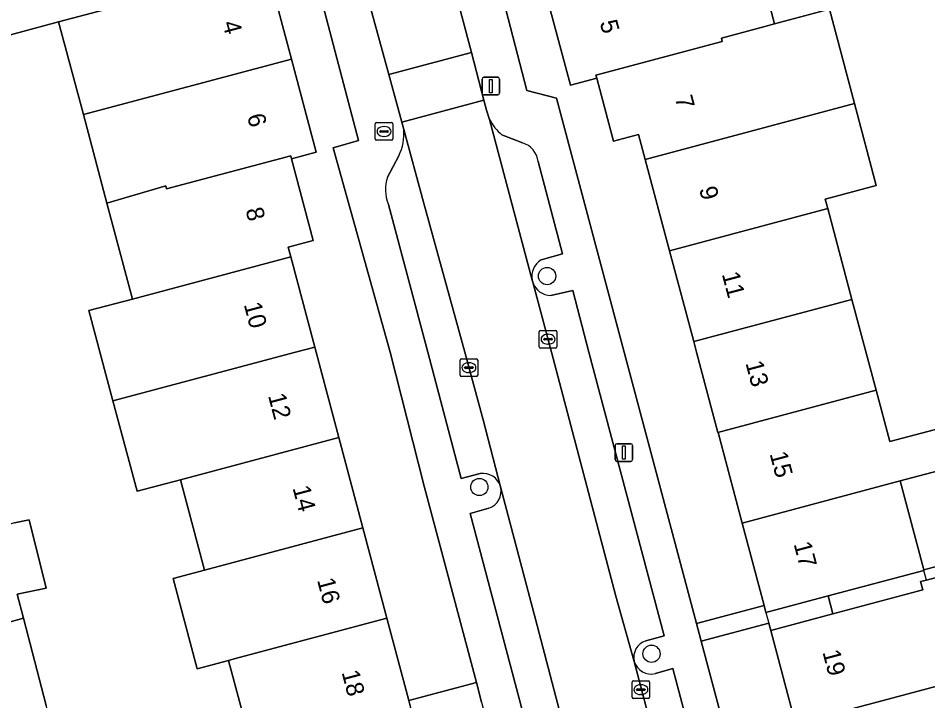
# Model space of a CAD drawing. Extents: x 162542 to 163147, y 380779 to 381521.
# Drawn here: x 162725.1 to 162776.8, y 380980.2 to 381019 of the extents above; entities that cross this region are included whole.
import ezdxf

# ---------------------------------------------------------------- set-up
doc = ezdxf.new("R2010")
doc.units = 0
for name, color, linetype in [('IMGEO_Boom', 7, 'Continuous'), ('IMGEO_Brandkraan', 7, 'Continuous'), ('IMGEO_Erf', 7, 'Continuous'), ('IMGEO_Kolk', 7, 'Continuous'), ('IMGEO_Lichtmast', 7, 'Continuous'), ('IMGEO_Pand', 7, 'Continuous'), ('IMGEO_Pand_nummerreeks', 7, 'Continuous'), ('IMGEO_Pand_overbouw', 7, 'Continuous'), ('IMGEO_Parkeervlak_open', 7, 'Continuous'), ('IMGEO_Rijbaan_lokaal_open', 7, 'Continuous'), ('IMGEO_Voetpad_open', 7, 'Continuous')]:
    doc.layers.add(name, color=color, linetype=linetype)

msp = doc.modelspace()

# ---------------------------------------------------------------- linework, layer by layer
at = {"layer": 'IMGEO_Boom'}
for centre in [(162755.19, 381004.332), (162751.341, 380992.348), (162761.127, 380982.876)]:
    msp.add_circle(centre, 0.489, dxfattribs=at)
at = {"layer": 'IMGEO_Brandkraan'}
for p, q in [((162745.423, 381012.122), (162745.423, 381012.974)), ((162745.498, 381013.048), (162746.35, 381013.048)), ((162745.911, 381012.828), (162745.936, 381012.828)), ((162746.424, 381012.974), (162746.424, 381012.122)), ((162745.682, 381012.542), (162745.682, 381012.554)), ((162746.12, 381012.505), (162745.722, 381012.505)), ((162745.725, 381012.591), (162746.123, 381012.591)), ((162745.934, 381012.268), (162745.909, 381012.268)), ((162746.166, 381012.554), (162746.166, 381012.542)), ((162746.35, 381012.048), (162745.498, 381012.048))]:
    msp.add_line(p, q, dxfattribs=at)
for points in [[(162745.423, 381012.122), (162745.423, 381012.974)], [(162745.498, 381013.048), (162746.35, 381013.048)], [(162746.424, 381012.974), (162746.424, 381012.122)], [(162746.35, 381012.048), (162745.498, 381012.048)]]:
    msp.add_lwpolyline(points, dxfattribs=at)
for centre, radius, start, end in [((162745.5, 381012.972), 0.0765, 91.552, 178.448), ((162745.5, 381012.972), 0.0765, 91.552, 178.448), ((162746.348, 381012.972), 0.0765, 1.552, 88.448), ((162746.348, 381012.972), 0.0765, 1.552, 88.448), ((162745.722, 381012.551), 0.0403, 85.8775, 175.7526), ((162745.719, 381012.541), 0.0366, 178.938, 274.7102), ((162746.123, 381012.548), 0.043, 264.8664, 352.4533), ((162746.127, 381012.553), 0.0386, 1.7309, 96.639), ((162745.5, 381012.124), 0.0765, 181.552, 268.448), ((162745.5, 381012.124), 0.0765, 181.552, 268.448), ((162746.348, 381012.124), 0.0765, 271.552, 358.448), ((162746.348, 381012.124), 0.0765, 271.552, 358.448)]:
    msp.add_arc(centre, radius, start, end, dxfattribs=at)
for centre, major_axis, ratio, start_param, end_param in [((162745.91, 381012.548), (-0.387, 0.002), 0.722429, 4.712389, 7.853982), ((162745.935, 381012.548), (-0.39, 0.002), 0.717154, 1.570796, 4.712389)]:
    msp.add_ellipse(centre, major_axis=major_axis, ratio=ratio, start_param=start_param, end_param=end_param, dxfattribs=at)
at = {"layer": 'IMGEO_Erf'}
for points in [[(162762.153, 381005.771), (162760.77, 381010.962), (162760.394, 381012.373), (162758.966, 381011.993), (162758.011, 381015.58), (162756.517, 381015.182), (162755.104, 381020.488), (162753.691, 381025.795), (162751.366, 381025.19), (162754.046, 381014.881), (162755.726, 381014.447), (162759.578, 381000), (162763.686, 380984.593), (162767.521, 380985.616), (162766.274, 380990.297), (162764.904, 380995.443), (162764.901, 380995.452), (162764.901, 380995.454), (162763.69, 381000), (162763.527, 381000.613)], [(162746.28, 381000), (162743.026, 381011.614), (162744.463, 381012.029), (162741.713, 381022.565), (162739.263, 381021.926), (162740.667, 381016.648), (162742.071, 381011.368), (162740.662, 381010.993), (162741.895, 381006.359), (162740.471, 381005.98), (162740.62, 381005.421), (162741.985, 381000.29), (162742.062, 381000), (162743.35, 380995.158), (162744.715, 380990.028), (162746.08, 380984.896), (162747.326, 380980.213), (162751.174, 380981.237), (162748.205, 380992.388)], [(162776.104, 380953.39), (162774.717, 380958.599), (162773.391, 380963.577), (162772.064, 380968.558), (162770.678, 380973.763), (162769.31, 380978.899), (162767.898, 380984.203), (162767.79, 380984.608), (162763.955, 380983.585), (162780.617, 380921.086), (162784.437, 380922.105), (162783.04, 380927.349), (162781.653, 380932.556), (162780.266, 380937.765), (162778.879, 380942.973), (162777.492, 380948.181)]]:
    msp.add_lwpolyline(points, close=True, dxfattribs=at)
for points in [[(162766.804, 381023.607), (162768.122, 381018.658), (162771.235, 381019.487), (162772.661, 381014.131), (162773.9, 381009.48), (162770.994, 381008.706), (162771.138, 381008.166), (162772.512, 381003.008), (162773.886, 380997.849), (162774.665, 380994.928), (162777.543, 380995.694)], [(162738.516, 380977.142), (162737.088, 380982.502), (162735.304, 380982.026), (162733.937, 380987.156), (162735.722, 380987.632), (162734.356, 380992.762), (162731.885, 380992.104), (162730.518, 380997.236), (162729.151, 381002.367), (162731.622, 381003.025), (162730.172, 381008.47), (162728.832, 381013.503), (162727.427, 381018.777), (162715.091, 381015.44)], [(162778.139, 380993.459), (162775.259, 380992.692), (162776.605, 380987.639), (162788.533, 380990.817)], [(162724.914, 380990.308), (162725.758, 380990.483), (162726.716, 380986.611), (162725.08, 380986.261), (162725.435, 380984.891), (162726.721, 380979.933)]]:
    msp.add_lwpolyline(points, dxfattribs=at)
at = {"layer": 'IMGEO_Kolk'}
for p, q in [((162754.744, 381000.318), (162754.744, 381001.17)), ((162754.819, 381001.244), (162755.671, 381001.244)), ((162755.232, 381001.024), (162755.257, 381001.024)), ((162755.745, 381001.17), (162755.745, 381000.318)), ((162755.003, 381000.738), (162755.003, 381000.75)), ((162755.441, 381000.701), (162755.043, 381000.701)), ((162755.046, 381000.787), (162755.444, 381000.787)), ((162755.255, 381000.464), (162755.23, 381000.464)), ((162755.487, 381000.75), (162755.487, 381000.738)), ((162755.671, 381000.244), (162754.819, 381000.244)), ((162750.245, 380998.705), (162750.245, 380999.557)), ((162750.32, 380999.631), (162751.172, 380999.631)), ((162750.733, 380999.411), (162750.758, 380999.411)), ((162751.246, 380999.557), (162751.246, 380998.705)), ((162750.504, 380999.125), (162750.504, 380999.137)), ((162750.942, 380999.088), (162750.544, 380999.088)), ((162750.547, 380999.174), (162750.945, 380999.174)), ((162750.756, 380998.851), (162750.731, 380998.851)), ((162750.988, 380999.137), (162750.988, 380999.125)), ((162751.172, 380998.631), (162750.32, 380998.631)), ((162760.018, 380980.407), (162760.018, 380981.259)), ((162760.093, 380981.333), (162760.945, 380981.333)), ((162761.019, 380981.259), (162761.019, 380980.407)), ((162760.277, 380980.827), (162760.277, 380980.839)), ((162760.715, 380980.79), (162760.317, 380980.79)), ((162760.32, 380980.876), (162760.718, 380980.876)), ((162760.506, 380981.113), (162760.531, 380981.113)), ((162760.761, 380980.839), (162760.761, 380980.827)), ((162760.945, 380980.333), (162760.093, 380980.333)), ((162760.529, 380980.553), (162760.504, 380980.553))]:
    msp.add_line(p, q, dxfattribs=at)
for points in [[(162754.744, 381000.318), (162754.744, 381001.17)], [(162754.819, 381001.244), (162755.671, 381001.244)], [(162755.745, 381001.17), (162755.745, 381000.318)], [(162755.671, 381000.244), (162754.819, 381000.244)], [(162750.245, 380998.705), (162750.245, 380999.557)], [(162750.32, 380999.631), (162751.172, 380999.631)], [(162751.246, 380999.557), (162751.246, 380998.705)], [(162751.172, 380998.631), (162750.32, 380998.631)], [(162760.018, 380980.407), (162760.018, 380981.259)], [(162760.093, 380981.333), (162760.945, 380981.333)], [(162761.019, 380981.259), (162761.019, 380980.407)], [(162760.945, 380980.333), (162760.093, 380980.333)]]:
    msp.add_lwpolyline(points, dxfattribs=at)
for centre, radius, start, end in [((162754.821, 381001.168), 0.0765, 91.552, 178.448), ((162754.821, 381001.168), 0.0765, 91.552, 178.448), ((162755.669, 381001.168), 0.0765, 1.552, 88.448), ((162755.669, 381001.168), 0.0765, 1.552, 88.448), ((162754.821, 381000.32), 0.0765, 181.552, 268.448), ((162754.821, 381000.32), 0.0765, 181.552, 268.448), ((162755.043, 381000.747), 0.0403, 85.8775, 175.7526), ((162755.04, 381000.737), 0.0366, 178.938, 274.7102), ((162755.444, 381000.744), 0.043, 264.8664, 352.4533), ((162755.448, 381000.749), 0.0386, 1.7309, 96.639), ((162755.669, 381000.32), 0.0765, 271.552, 358.448), ((162755.669, 381000.32), 0.0765, 271.552, 358.448), ((162750.322, 380999.555), 0.0765, 91.552, 178.448), ((162750.322, 380999.555), 0.0765, 91.552, 178.448), ((162751.17, 380999.555), 0.0765, 1.552, 88.448), ((162751.17, 380999.555), 0.0765, 1.552, 88.448), ((162750.544, 380999.134), 0.0403, 85.8775, 175.7526), ((162750.541, 380999.124), 0.0366, 178.938, 274.7102), ((162750.945, 380999.131), 0.043, 264.8664, 352.4533), ((162750.949, 380999.136), 0.0386, 1.7309, 96.639), ((162750.322, 380998.707), 0.0765, 181.552, 268.448), ((162750.322, 380998.707), 0.0765, 181.552, 268.448), ((162751.17, 380998.707), 0.0765, 271.552, 358.448), ((162751.17, 380998.707), 0.0765, 271.552, 358.448), ((162760.095, 380981.257), 0.0765, 91.552, 178.448), ((162760.095, 380981.257), 0.0765, 91.552, 178.448), ((162760.943, 380981.257), 0.0765, 1.552, 88.448), ((162760.943, 380981.257), 0.0765, 1.552, 88.448), ((162760.317, 380980.836), 0.0403, 85.8775, 175.7526), ((162760.314, 380980.826), 0.0366, 178.938, 274.7102), ((162760.718, 380980.833), 0.043, 264.8664, 352.4533), ((162760.722, 380980.838), 0.0386, 1.7309, 96.639), ((162760.095, 380980.409), 0.0765, 181.552, 268.448), ((162760.095, 380980.409), 0.0765, 181.552, 268.448), ((162760.943, 380980.409), 0.0765, 271.552, 358.448), ((162760.943, 380980.409), 0.0765, 271.552, 358.448)]:
    msp.add_arc(centre, radius, start, end, dxfattribs=at)
for centre, major_axis, ratio, start_param, end_param in [((162755.231, 381000.744), (-0.387, 0.002), 0.722429, 4.712389, 7.853982), ((162755.256, 381000.744), (-0.39, 0.002), 0.717154, 1.570796, 4.712389), ((162750.732, 380999.131), (-0.387, 0.002), 0.722429, 4.712389, 7.853982), ((162750.757, 380999.131), (-0.39, 0.002), 0.717154, 1.570796, 4.712389), ((162760.505, 380980.833), (-0.387, 0.002), 0.722429, 4.712389, 7.853982), ((162760.53, 380980.833), (-0.39, 0.002), 0.717154, 1.570796, 4.712389)]:
    msp.add_ellipse(centre, major_axis=major_axis, ratio=ratio, start_param=start_param, end_param=end_param, dxfattribs=at)
at = {"layer": 'IMGEO_Lichtmast'}
for p, q in [((162751.492, 381014.725), (162751.492, 381015.525)), ((162751.492, 381015.525), (162751.492, 381014.725)), ((162751.592, 381015.625), (162752.382, 381015.625)), ((162752.382, 381015.625), (162751.592, 381015.625)), ((162752.482, 381015.525), (162752.482, 381014.725)), ((162752.482, 381014.725), (162752.482, 381015.525)), ((162752.382, 381014.625), (162751.592, 381014.625)), ((162751.592, 381014.625), (162752.382, 381014.625)), ((162759.057, 380993.905), (162759.057, 380994.705)), ((162759.057, 380994.705), (162759.057, 380993.905)), ((162759.157, 380994.805), (162759.947, 380994.805)), ((162759.947, 380994.805), (162759.157, 380994.805)), ((162760.047, 380994.705), (162760.047, 380993.905)), ((162760.047, 380993.905), (162760.047, 380994.705)), ((162759.947, 380993.805), (162759.157, 380993.805)), ((162759.157, 380993.805), (162759.947, 380993.805))]:
    msp.add_line(p, q, dxfattribs=at)
for points in [[(162751.912, 381015.5), (162752.062, 381015.5), (162752.062, 381014.75), (162751.912, 381014.75), (162751.912, 381015.5)], [(162759.477, 380994.68), (162759.627, 380994.68), (162759.627, 380993.93), (162759.477, 380993.93), (162759.477, 380994.68)]]:
    msp.add_lwpolyline(points, dxfattribs=at)
for centre, start, end in [((162751.592, 381015.525), 90, 180), ((162751.592, 381015.525), 90, 180), ((162752.382, 381015.525), 0, 90), ((162752.382, 381015.525), 360, 90), ((162751.592, 381014.725), 180, 270), ((162751.592, 381014.725), 180, 270), ((162752.382, 381014.725), 270, 0), ((162752.382, 381014.725), 270, 0), ((162759.157, 380994.705), 90, 180), ((162759.157, 380994.705), 90, 180), ((162759.947, 380994.705), 0, 90), ((162759.947, 380994.705), 360, 90), ((162759.157, 380993.905), 180, 270), ((162759.157, 380993.905), 180, 270), ((162759.947, 380993.905), 270, 0), ((162759.947, 380993.905), 270, 0)]:
    msp.add_arc(centre, 0.1, start, end, dxfattribs=at)
at = {"layer": 'IMGEO_Pand'}
for points in [[(162767.564, 381018.509), (162768.122, 381018.658), (162766.804, 381023.607), (162763.77, 381022.798), (162755.104, 381020.488), (162756.517, 381015.182), (162758.011, 381015.58), (162757.964, 381015.749), (162765.147, 381017.666), (162765.096, 381017.852)], [(162727.427, 381018.777), (162728.832, 381013.503), (162740.667, 381016.648), (162739.263, 381021.926), (162734.432, 381020.641), (162730.443, 381019.58)], [(162771.235, 381019.487), (162768.122, 381018.658), (162767.564, 381018.509), (162765.096, 381017.852), (162765.147, 381017.666), (162757.964, 381015.749), (162758.011, 381015.58), (162758.966, 381011.993), (162760.394, 381012.373), (162760.77, 381010.962), (162772.661, 381014.131)], [(162730.172, 381008.47), (162733.516, 381009.456), (162733.561, 381009.288), (162740.616, 381011.164), (162740.662, 381010.993), (162742.071, 381011.368), (162740.667, 381016.648), (162728.832, 381013.503)], [(162760.77, 381010.962), (162762.153, 381005.771), (162771.138, 381008.166), (162770.994, 381008.706), (162773.9, 381009.48), (162772.661, 381014.131)], [(162731.622, 381003.025), (162740.62, 381005.421), (162740.471, 381005.98), (162741.895, 381006.359), (162740.662, 381010.993), (162740.616, 381011.164), (162733.561, 381009.288), (162733.516, 381009.456), (162730.172, 381008.47)], [(162772.512, 381003.008), (162771.138, 381008.166), (162762.153, 381005.771), (162763.527, 381000.613)], [(162729.151, 381002.367), (162730.518, 380997.236), (162740.895, 381000), (162741.985, 381000.29), (162740.62, 381005.421), (162731.622, 381003.025)], [(162772.512, 381003.008), (162763.527, 381000.613), (162763.69, 381000), (162764.901, 380995.454), (162764.901, 380995.452), (162773.886, 380997.849)], [(162731.885, 380992.104), (162734.356, 380992.762), (162743.35, 380995.158), (162742.062, 381000), (162741.985, 381000.29), (162740.895, 381000), (162730.518, 380997.236)], [(162773.886, 380997.849), (162764.901, 380995.452), (162764.904, 380995.443), (162766.274, 380990.297), (162775.259, 380992.692), (162778.139, 380993.459), (162777.543, 380995.694), (162774.665, 380994.928)], [(162735.722, 380987.632), (162744.715, 380990.028), (162743.35, 380995.158), (162734.356, 380992.762)], [(162775.259, 380992.692), (162766.274, 380990.297), (162767.521, 380985.616), (162767.628, 380985.216), (162771.168, 380986.161), (162776.612, 380987.614), (162776.605, 380987.639)], [(162722.049, 380989.483), (162723.423, 380984.355), (162725.435, 380984.891), (162725.08, 380986.261), (162726.716, 380986.611), (162725.758, 380990.483), (162724.914, 380990.308)], [(162735.722, 380987.632), (162733.937, 380987.156), (162735.304, 380982.026), (162737.088, 380982.502), (162737.405, 380982.586), (162746.08, 380984.896), (162744.715, 380990.028)], [(162779.767, 380987.412), (162779.654, 380987.837), (162776.758, 380987.065), (162776.416, 380986.974), (162776.539, 380986.511), (162771.439, 380985.144), (162767.898, 380984.203), (162769.31, 380978.899), (162781.192, 380982.065)], [(162725.435, 380984.891), (162723.423, 380984.355), (162724.752, 380979.397), (162725.239, 380979.472), (162725.272, 380979.355), (162726.768, 380979.754), (162726.721, 380979.933)], [(162746.08, 380984.896), (162737.405, 380982.586), (162737.088, 380982.502), (162738.516, 380977.142), (162738.584, 380976.886), (162738.901, 380976.971), (162738.772, 380977.454), (162743.687, 380978.763), (162747.443, 380979.774), (162747.326, 380980.213)], [(162781.192, 380982.065), (162769.31, 380978.899), (162770.678, 380973.763), (162779.663, 380976.158), (162782.56, 380976.93)]]:
    msp.add_lwpolyline(points, close=True, dxfattribs=at)
at = {"layer": 'IMGEO_Pand_overbouw'}
for points in [[(162776.539, 380986.511), (162776.416, 380986.974), (162776.758, 380987.065), (162776.612, 380987.614), (162771.168, 380986.161), (162771.439, 380985.144)], [(162771.168, 380986.161), (162767.628, 380985.216), (162767.898, 380984.203), (162771.439, 380985.144)]]:
    msp.add_lwpolyline(points, close=True, dxfattribs=at)
at = {"layer": 'IMGEO_Parkeervlak_open'}
for points in [[(162751.918, 381013.227), (162754.344, 381004.096)], [(162752.55, 380992.366), (162751.554, 380996.167), (162750.511, 381000), (162748.173, 381008.523), (162747.039, 381012.667)], [(162753.793, 381011.903), (162752.619, 381012.362)], [(162746.764, 381011.167), (162746.127, 381009.956)], [(162754.851, 381005.249), (162756.074, 381005.602), (162754.681, 381010.838)], [(162746.171, 381008.407), (162748.414, 381000), (162750.303, 380992.827), (162751.381, 380993.109)], [(162754.376, 381003.979), (162755.445, 381000), (162759.103, 380986.155), (162760.137, 380982.439)], [(162760.794, 380983.617), (162761.847, 380983.899), (162757.571, 381000), (162756.644, 381003.513), (162755.396, 381003.236)], [(162758.21, 380970.847), (162757.798, 380972.409), (162754.617, 380984.472), (162752.55, 380992.366)], [(162751.88, 380991.141), (162750.814, 380990.847), (162756.005, 380971.24), (162757.033, 380971.534)], [(162760.137, 380982.439), (162762.449, 380973.645), (162764.42, 380974.169), (162762.333, 380982.033), (162761.343, 380981.752)]]:
    msp.add_lwpolyline(points, dxfattribs=at)
for centre, radius, start, end in [((162754.602, 381014.686), 3.055, 208.522, 229.521), ((162744.364, 381012.382), 2.69, 333.1449, 6.0774), ((162753.401, 381010.673), 1.291, 7.3376, 72.3053), ((162748.16, 381009.239), 2.156, 160.5603, 202.6938), ((162755.405, 381004.317), 1.084, 120.7462, 191.7814), ((162755.402, 381004.315), 1.079, 198.1584, 269.7001), ((162751.541, 380992.069), 1.052, 16.3956, 98.7255), ((162751.527, 380992.13), 1.05, 289.6652, 12.9828), ((162761.134, 380982.655), 1.02, 109.4683, 192.2327), ((162761.109, 380982.743), 1.018, 197.3572, 283.3066)]:
    msp.add_arc(centre, radius, start, end, dxfattribs=at)
at = {"layer": 'IMGEO_Rijbaan_lokaal_open'}
for points in [[(162747.763, 381028.676), (162746.385, 381033.726), (162744.671, 381040.096), (162744.439, 381040.9), (162739.698, 381039.707), (162739.733, 381039.548), (162743.577, 381025.319), (162746.189, 381015.774), (162750.888, 381017.029), (162749.402, 381022.671), (162748.74, 381025.096)], [(162751.602, 381014.32), (162750.888, 381017.029), (162746.189, 381015.774), (162746.928, 381013.073)], [(162751.602, 381014.32), (162746.928, 381013.073), (162747.039, 381012.667), (162748.173, 381008.523), (162750.511, 381000), (162751.554, 380996.167), (162752.55, 380992.366), (162754.617, 380984.472), (162757.798, 380972.409), (162762.449, 380973.645), (162760.137, 380982.439), (162759.103, 380986.155), (162755.445, 381000), (162754.376, 381003.979), (162754.344, 381004.096), (162751.918, 381013.227), (162751.752, 381013.749)]]:
    msp.add_lwpolyline(points, close=True, dxfattribs=at)
at = {"layer": 'IMGEO_Voetpad_open'}
for points in [[(162784.888, 380889.476), (162785.006, 380889.053), (162785.664, 380886.45), (162788.238, 380876.778), (162790.799, 380877.498), (162790.444, 380878.831), (162787.726, 380889.027), (162787.979, 380889.585), (162788.858, 380889.82), (162787.754, 380894.316), (162780.832, 380920.278), (162780.617, 380921.086), (162763.955, 380983.585), (162763.686, 380984.593), (162759.578, 381000), (162755.726, 381014.447), (162754.046, 381014.881), (162751.366, 381025.19), (162751.014, 381026.543), (162750.404, 381028.836), (162749.506, 381032.166), (162746.399, 381043.845)], [(162739.036, 381041.753), (162736.762, 381041.139), (162739.873, 381029.488), (162740.737, 381026.252), (162741.338, 381024.003), (162741.713, 381022.565), (162744.463, 381012.029), (162743.026, 381011.614), (162746.28, 381000), (162748.205, 380992.388), (162751.174, 380981.237), (162751.467, 380980.135), (162767.943, 380918.262), (162768.14, 380917.522), (162776.41, 380886.464), (162777.36, 380886.698), (162778.067, 380886.244), (162780.774, 380876.082), (162781.077, 380874.945), (162783.57, 380875.561), (162782.851, 380878.347), (162780.982, 380885.195), (162780.272, 380887.798)], [(162744.205, 381041.709), (162744.439, 381040.9), (162744.671, 381040.096), (162746.385, 381033.726), (162747.763, 381028.676), (162748.243, 381028.813), (162749.22, 381025.233), (162748.74, 381025.096), (162749.402, 381022.671), (162750.888, 381017.029), (162751.602, 381014.32), (162751.752, 381013.749), (162751.918, 381013.227)], [(162747.039, 381012.667), (162746.928, 381013.073), (162746.189, 381015.774), (162743.577, 381025.319), (162739.733, 381039.548), (162739.698, 381039.707), (162739.513, 381040.561)], [(162715.091, 381015.44), (162727.427, 381018.777), (162730.443, 381019.58), (162734.432, 381020.641), (162739.263, 381021.926), (162741.713, 381022.565), (162741.338, 381024.003), (162737.298, 381022.924), (162733.576, 381021.93), (162730.454, 381021.097), (162730.475, 381021.018), (162726.95, 381020.076), (162723.158, 381019.064)], [(162752.619, 381012.362), (162753.793, 381011.903)], [(162746.127, 381009.956), (162746.764, 381011.167)], [(162754.681, 381010.838), (162756.074, 381005.602), (162754.851, 381005.249)], [(162751.381, 380993.109), (162750.303, 380992.827), (162748.414, 381000), (162746.171, 381008.407)], [(162754.344, 381004.096), (162754.376, 381003.979)], [(162755.396, 381003.236), (162756.644, 381003.513), (162757.571, 381000), (162761.847, 380983.899), (162760.794, 380983.617)], [(162757.033, 380971.534), (162756.005, 380971.24), (162750.814, 380990.847), (162751.88, 380991.141)], [(162788.533, 380990.817), (162776.605, 380987.639), (162776.612, 380987.614), (162771.168, 380986.161), (162767.628, 380985.216), (162767.521, 380985.616), (162763.686, 380984.593), (162763.955, 380983.585), (162767.79, 380984.608), (162767.898, 380984.203), (162771.439, 380985.144), (162776.539, 380986.511), (162776.416, 380986.974), (162776.758, 380987.065), (162779.654, 380987.837)], [(162761.343, 380981.752), (162762.333, 380982.033), (162764.42, 380974.169), (162765.084, 380971.665), (162767.792, 380961.461), (162766.904, 380961.192)], [(162751.467, 380980.135), (162751.174, 380981.237), (162747.326, 380980.213), (162747.443, 380979.774)]]:
    msp.add_lwpolyline(points, dxfattribs=at)
for centre, radius, start, end in [((162754.602, 381014.686), 3.055, 208.522, 229.521), ((162744.364, 381012.382), 2.69, 333.1449, 6.0774), ((162753.401, 381010.673), 1.291, 7.3376, 72.3053), ((162748.16, 381009.239), 2.156, 160.5603, 202.6938), ((162755.405, 381004.317), 1.084, 120.7462, 191.7814), ((162755.402, 381004.315), 1.079, 198.1584, 269.7001), ((162751.541, 380992.069), 1.052, 16.3956, 98.7255), ((162751.527, 380992.13), 1.05, 289.6652, 12.9828), ((162761.134, 380982.655), 1.02, 109.4683, 192.2327), ((162761.109, 380982.743), 1.018, 197.3572, 283.3066)]:
    msp.add_arc(centre, radius, start, end, dxfattribs=at)

# ---------------------------------------------------------------- texts
at = {"layer": 'IMGEO_Pand_nummerreeks'}
for s, rotation, p in [('5', 284.9082, (162758.174, 381018.749)), ('4', 284.8936, (162736.724, 381018.709)), ('7', 284.9139, (162762.445, 381014.461)), ('6', 284.8936, (162738.128, 381013.43)), ('9', 284.9164, (162763.822, 381009.289)), ('8', 284.8999, (162738.039, 381008.094)), ('11', 284.9164, (162765.113, 381004.45)), ('10', 284.8986, (162737.945, 381002.72)), ('13', 284.9139, (162766.459, 380999.393)), ('12', 284.8963, (162739.322, 380997.541)), ('15', 284.9139, (162767.833, 380994.235)), ('14', 284.8963, (162740.717, 380992.299)), ('17', 284.9139, (162769.196, 380989.116)), ('16', 284.8963, (162742.11, 380987.06)), ('19', 284.9139, (162770.833, 380982.972)), ('18', 284.8967, (162743.505, 380981.818))]:
    msp.add_text(s, height=1, rotation=rotation, dxfattribs=at).set_placement(p)

doc.saveas('drawing.dxf')
